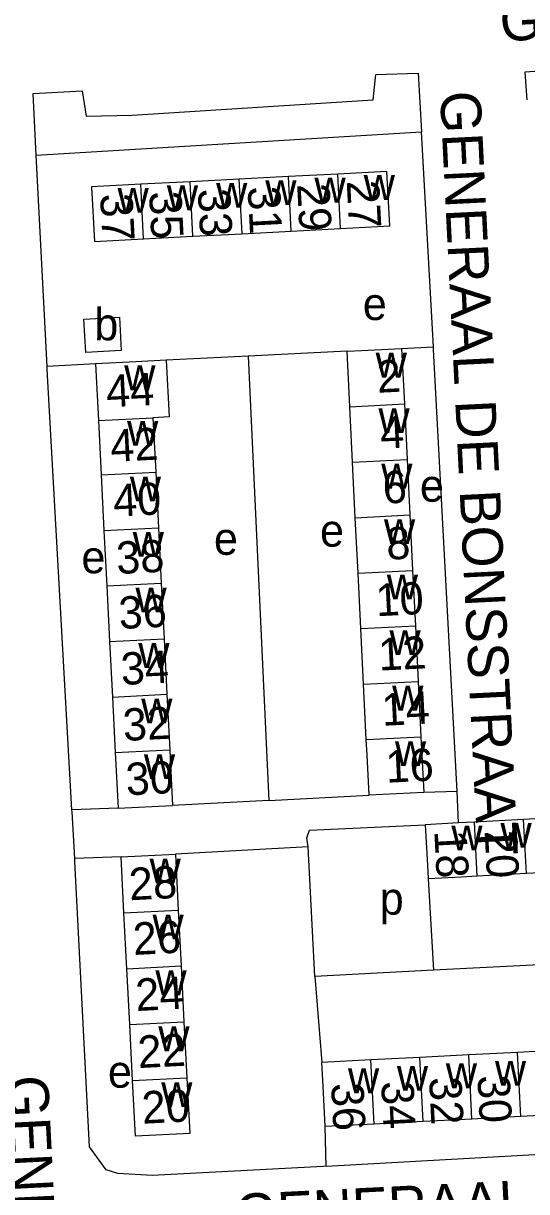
# Model space of a CAD drawing. Extents: x 159294 to 161936, y 384538 to 386517.
# Drawn here: x 161621.7 to 161684, y 385864.1 to 386008.7 of the extents above; entities that cross this region are included whole.
import ezdxf

# ---------------------------------------------------------------- set-up
doc = ezdxf.new("R2010")
doc.units = 0
for name, color, linetype in [('BLT_Basislijn', 7, 'Continuous'), ('BLT_Bebouwing', 7, 'Continuous'), ('BLT_Centroide', 7, 'Continuous'), ('BLT_Huisnummer', 7, 'Continuous'), ('BLT_Huisnummer_ tussenligend', 7, 'Continuous'), ('BLT_Onderverdeling_panden', 7, 'Continuous'), ('BLT_Straatnaam', 7, 'Continuous')]:
    doc.layers.add(name, color=color, linetype=linetype)

msp = doc.modelspace()

# ---------------------------------------------------------------- linework, layer by layer
at = {"layer": 'BLT_Basislijn'}
for p, q in [((161623.25, 385992.37), (161670.98, 385995.25)), ((161672.48, 385968.67), (161670.98, 385995.25)), ((161624.62, 385966.23), (161623.25, 385992.37)), ((161668.53, 385968.45), (161672.48, 385968.67)), ((161649.52, 385967.5), (161639.36, 385966.99)), ((161661.77, 385968.11), (161649.52, 385967.5)), ((161649.52, 385967.5), (161652.1, 385912.51)), ((161630.62, 385966.55), (161624.62, 385966.23)), ((161675.42, 385913.61), (161671.26, 385913.49)), ((161675.59, 385909.72), (161675.42, 385913.61)), ((161652.1, 385912.51), (161640.16, 385911.89)), ((161652.1, 385912.51), (161664.49, 385913.16)), ((161633.4, 385911.54), (161627.7, 385911.34)), ((161656.96, 385906.75), (161640.5, 385905.85)), ((161657.79, 385890.72), (161656.96, 385906.75)), ((161633.78, 385905.51), (161628.05, 385905.31)), ((161671.82, 385902.8), (161672.47, 385891.51)), ((161708.77, 385893.33), (161672.47, 385891.51)), ((161672.47, 385891.51), (161657.79, 385890.72)), ((161657.79, 385890.72), (161658.64, 385880.08)), ((161659.2, 385867.22), (161659.04, 385872.13)), ((161659.2, 385867.22), (161732.11, 385871.37))]:
    msp.add_line(p, q, dxfattribs=at)
for points in [[(161700.35, 386003.76), (161683.77, 386002.64), (161684.04, 385999.23)], [(161623.25, 385992.37), (161622.88, 385999.99), (161628.96, 386000.36), (161629.45, 385997.21), (161635.15, 385997.32), (161665.01, 385999.23), (161665.34, 386002.38), (161670.58, 386002.54), (161670.98, 385995.25)], [(161675.42, 385913.61), (161672.49, 385968.33), (161672.48, 385968.67)], [(161627.7, 385911.34), (161624.64, 385965.86), (161624.62, 385966.23)], [(161628.05, 385905.31), (161627.72, 385911.08), (161627.7, 385911.34)], [(161656.96, 385906.75), (161656.77, 385907.88), (161657.13, 385908.83), (161671.46, 385909.5)], [(161659.2, 385867.22), (161658.8, 385867.19), (161637.61, 385866.1), (161633.37, 385866.33), (161631.95, 385866.8), (161629.88, 385869.65), (161628.07, 385904.95), (161628.05, 385905.31)]]:
    msp.add_lwpolyline(points, dxfattribs=at)
at = {"layer": 'BLT_Bebouwing'}
for p, q in [((161660.61, 385990.04), (161654.51, 385989.72)), ((161642.32, 385989.09), (161636.22, 385988.77)), ((161648.42, 385989.4), (161642.32, 385989.09)), ((161654.51, 385989.72), (161648.42, 385989.4)), ((161648.77, 385982.66), (161654.86, 385982.98)), ((161654.86, 385982.98), (161660.96, 385983.3)), ((161636.57, 385982.03), (161642.67, 385982.35)), ((161642.67, 385982.35), (161648.77, 385982.66)), ((161668.53, 385968.45), (161668.87, 385961.58)), ((161662.11, 385961.24), (161661.77, 385968.11)), ((161630.62, 385966.55), (161630.98, 385959.54)), ((161662.45, 385954.37), (161662.11, 385961.24)), ((161668.87, 385961.58), (161669.21, 385954.71)), ((161637.73, 385959.88), (161638.07, 385953.14)), ((161630.98, 385959.54), (161631.32, 385952.8)), ((161662.79, 385947.5), (161662.45, 385954.37)), ((161669.21, 385954.71), (161669.55, 385947.84)), ((161631.32, 385952.8), (161631.66, 385945.92)), ((161638.07, 385953.14), (161638.42, 385946.26)), ((161663.13, 385940.63), (161662.79, 385947.5)), ((161669.55, 385947.84), (161669.89, 385940.97)), ((161631.66, 385945.92), (161632.01, 385939.05)), ((161638.42, 385946.26), (161638.76, 385939.39)), ((161669.89, 385940.97), (161670.23, 385934.1)), ((161638.76, 385939.39), (161639.11, 385932.51)), ((161663.47, 385933.77), (161663.13, 385940.63)), ((161632.01, 385939.05), (161632.36, 385932.17)), ((161663.81, 385926.9), (161663.47, 385933.77)), ((161670.23, 385934.1), (161670.57, 385927.23)), ((161632.36, 385932.17), (161632.71, 385925.3)), ((161639.11, 385932.51), (161639.46, 385925.64)), ((161664.15, 385920.03), (161663.81, 385926.9)), ((161670.57, 385927.23), (161670.91, 385920.36)), ((161632.71, 385925.3), (161633.06, 385918.42)), ((161639.46, 385925.64), (161639.81, 385918.76)), ((161670.91, 385920.36), (161671.26, 385913.49)), ((161633.06, 385918.42), (161633.4, 385911.54)), ((161671.26, 385913.49), (161664.49, 385913.16)), ((161633.4, 385911.54), (161640.16, 385911.89)), ((161689.72, 385910.47), (161683.64, 385910.15)), ((161675.59, 385909.72), (161671.46, 385909.5)), ((161677.55, 385909.83), (161675.59, 385909.72)), ((161683.64, 385910.15), (161677.55, 385909.83)), ((161633.78, 385905.51), (161640.5, 385905.85)), ((161634.13, 385898.59), (161633.78, 385905.51)), ((161640.5, 385905.85), (161640.86, 385898.94)), ((161683.99, 385903.45), (161677.9, 385903.13)), ((161690.08, 385903.77), (161683.99, 385903.45)), ((161640.86, 385898.94), (161641.21, 385892.02)), ((161634.49, 385891.68), (161634.13, 385898.59)), ((161634.85, 385884.76), (161634.49, 385891.68)), ((161641.21, 385892.02), (161641.57, 385885.11)), ((161635.2, 385877.85), (161634.85, 385884.76)), ((161641.57, 385885.11), (161641.93, 385878.19)), ((161688.97, 385881.63), (161682.9, 385881.32)), ((161664.7, 385880.39), (161658.64, 385880.08)), ((161670.77, 385880.7), (161664.7, 385880.39)), ((161676.84, 385881.01), (161670.77, 385880.7)), ((161682.9, 385881.32), (161676.84, 385881.01)), ((161677.24, 385873.06), (161671.18, 385872.75)), ((161683.31, 385873.37), (161677.24, 385873.06)), ((161689.37, 385873.68), (161683.31, 385873.37)), ((161665.11, 385872.44), (161659.04, 385872.13)), ((161671.18, 385872.75), (161665.11, 385872.44))]:
    msp.add_line(p, q, dxfattribs=at)
for points in [[(161660.96, 385983.3), (161667.05, 385983.61), (161666.7, 385990.35), (161660.61, 385990.04)], [(161636.22, 385988.77), (161630.13, 385988.45), (161630.48, 385981.71), (161636.57, 385982.03)], [(161661.77, 385968.11), (161663.54, 385968.2), (161668.53, 385968.45)], [(161639.36, 385966.99), (161635.61, 385966.8), (161630.62, 385966.55)], [(161639.36, 385966.99), (161639.72, 385959.98), (161637.73, 385959.88)], [(161664.49, 385913.16), (161664.24, 385918.15), (161664.15, 385920.03)], [(161639.81, 385918.76), (161639.9, 385916.88), (161640.16, 385911.89)], [(161671.46, 385909.5), (161671.73, 385904.51), (161671.82, 385902.8)], [(161677.9, 385903.13), (161675.93, 385903.02), (161671.82, 385902.8)], [(161659.04, 385872.13), (161658.79, 385877.13), (161658.64, 385880.08)], [(161641.93, 385878.19), (161642.28, 385871.28), (161635.56, 385870.93), (161635.2, 385877.85)]]:
    msp.add_lwpolyline(points, dxfattribs=at)
msp.add_lwpolyline([(161629.18, 385972.08), (161633.58, 385972.32), (161633.8, 385968.18), (161629.41, 385967.94)], close=True, dxfattribs=at)
at = {"layer": 'BLT_Onderverdeling_panden'}
for p, q in [((161660.96, 385983.3), (161660.61, 385990.04)), ((161636.57, 385982.03), (161636.22, 385988.77)), ((161642.67, 385982.35), (161642.32, 385989.09)), ((161648.77, 385982.66), (161648.42, 385989.4)), ((161654.86, 385982.98), (161654.51, 385989.72)), ((161662.11, 385961.24), (161668.87, 385961.58)), ((161630.98, 385959.54), (161637.73, 385959.88)), ((161662.45, 385954.37), (161669.21, 385954.71)), ((161631.32, 385952.8), (161638.07, 385953.14)), ((161662.79, 385947.5), (161669.55, 385947.84)), ((161631.66, 385945.92), (161638.42, 385946.26)), ((161663.13, 385940.63), (161669.89, 385940.97)), ((161632.01, 385939.05), (161638.76, 385939.39)), ((161663.47, 385933.77), (161670.23, 385934.1)), ((161632.36, 385932.17), (161639.11, 385932.51)), ((161663.81, 385926.9), (161670.57, 385927.23)), ((161632.71, 385925.3), (161639.46, 385925.64)), ((161664.15, 385920.03), (161670.91, 385920.36)), ((161633.06, 385918.42), (161639.81, 385918.76)), ((161677.9, 385903.13), (161677.55, 385909.83)), ((161683.99, 385903.45), (161683.64, 385910.15)), ((161634.13, 385898.59), (161640.86, 385898.94)), ((161634.49, 385891.68), (161641.21, 385892.02)), ((161634.85, 385884.76), (161641.57, 385885.11)), ((161665.11, 385872.44), (161664.7, 385880.39)), ((161671.18, 385872.75), (161670.77, 385880.7)), ((161677.24, 385873.06), (161676.84, 385881.01)), ((161683.31, 385873.37), (161682.9, 385881.32)), ((161635.2, 385877.85), (161641.93, 385878.19))]:
    msp.add_line(p, q, dxfattribs=at)

# ---------------------------------------------------------------- texts
at = {"layer": 'BLT_Centroide'}
for s, p in [('w', (161639.45, 385985.56)), ('w', (161645.55, 385985.88)), ('w', (161651.64, 385986.19)), ('w', (161657.73, 385986.5)), ('w', (161663.83, 385986.83)), ('w', (161633.34, 385985.25)), ('e', (161663.72, 385971.97)), ('b', (161630.46, 385969.46)), ('w', (161665.31, 385964.84)), ('w', (161634.17, 385963.28)), ('w', (161665.66, 385957.97)), ('w', (161634.52, 385956.41)), ('w', (161666, 385951.11)), ('w', (161634.86, 385949.53)), ('e', (161670.79, 385949.48)), ('e', (161658.42, 385943.92)), ('w', (161666.34, 385944.23)), ('w', (161635.22, 385942.66)), ('e', (161645.28, 385942.91)), ('e', (161628.87, 385940.63)), ('w', (161666.69, 385937.38)), ('w', (161635.56, 385935.78)), ('w', (161667.02, 385930.5)), ('w', (161635.91, 385928.91)), ('w', (161667.36, 385923.62)), ('w', (161636.27, 385922.03)), ('w', (161667.7, 385916.75)), ('w', (161636.61, 385915.16)), ('w', (161674.69, 385906.33)), ('w', (161680.77, 385906.64)), ('w', (161637.31, 385902.22)), ('p', (161665.81, 385898.37)), ('w', (161637.67, 385895.31)), ('w', (161638.03, 385888.39)), ('w', (161638.39, 385881.47)), ('e', (161632.15, 385876.95)), ('w', (161680.08, 385877.2)), ('w', (161661.88, 385876.27)), ('w', (161667.94, 385876.58)), ('w', (161674, 385876.89)), ('w', (161638.75, 385874.56))]:
    msp.add_text(s, height=4, dxfattribs=at).set_placement(p)
at = {"layer": 'BLT_Huisnummer'}
for s, rotation, p in [('27', 272.9811, (161661.72, 385989.17)), ('37', 272.9811, (161631.18, 385987.55)), ('31', 272.9811, (161649.45, 385988.44)), ('2', 2.8366, (161665.55, 385962.96)), ('44', 2.8996, (161632.02, 385961.16)), ('6', 2.8366, (161666.28, 385949.23)), ('38', 2.8996, (161633.27, 385940.52)), ('10', 2.8366, (161665.4, 385935.3)), ('34', 2.8996, (161633.84, 385926.79)), ('16', 2.8366, (161666.64, 385914.69)), ('30', 2.8996, (161634.45, 385913.13)), ('18', 273.0152, (161672.57, 385908.73)), ('28', 2.9461, (161634.85, 385900.14)), ('24', 2.9461, (161635.65, 385886.43)), ('36', 272.9246, (161659.79, 385877.46)), ('30', 272.9246, (161677.91, 385878.43)), ('20', 2.9461, (161636.44, 385872.48))]:
    msp.add_text(s, height=4, rotation=rotation, dxfattribs=at).set_placement(p)
at = {"layer": 'BLT_Huisnummer_ tussenligend'}
for s, rotation, p in [('29', 272.9811, (161655.58, 385988.79)), ('35', 272.9811, (161637.24, 385987.83)), ('33', 272.9811, (161643.28, 385988.15)), ('4', 2.8366, (161665.96, 385956.02)), ('42', 2.8996, (161632.54, 385954.4)), ('40', 2.8996, (161632.89, 385947.62)), ('8', 2.8366, (161666.71, 385942.29)), ('36', 2.8996, (161633.58, 385933.72)), ('12', 2.8366, (161665.74, 385928.57)), ('14', 2.8366, (161666.14, 385921.74)), ('32', 2.8996, (161634.1, 385919.86)), ('20', 273.0152, (161678.8, 385908.72)), ('26', 2.9461, (161635.34, 385893.37)), ('22', 2.9461, (161635.93, 385879.37)), ('34', 272.9246, (161665.99, 385877.69)), ('32', 272.9246, (161671.92, 385878.2))]:
    msp.add_text(s, height=4, rotation=rotation, dxfattribs=at).set_placement(p)
at = {"layer": 'BLT_Straatnaam'}
for s, rotation, p in [('GENERAAL DIEMONTSTRAAT', 3.0969, (161680.81, 386006.45)), ('GENERAAL DE BONSSTRAAT', 272.8206, (161673.28, 386000.21)), ('GENERAAL MARSHALLWEG', 272.8724, (161619.72, 385878.35)), ('GENERAAL VAN NIJNATTENSTRAAT', 2.8083, (161648.05, 385858.76))]:
    msp.add_text(s, height=5, rotation=rotation, dxfattribs=at).set_placement(p)

doc.saveas('drawing.dxf')
